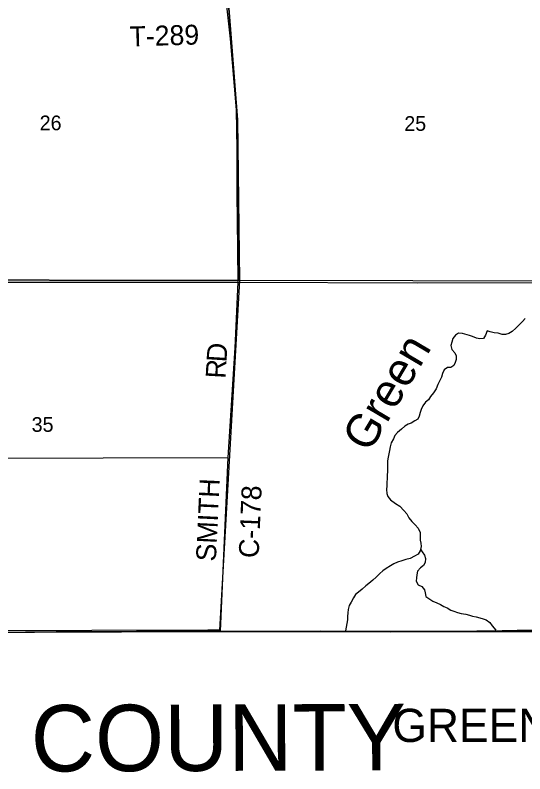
# Model space of a CAD drawing. Extents: x 1588073 to 2013523, y 1090242 to 1357120.
# Drawn here: x 1802549 to 1810221, y 1184806 to 1196224 of the extents above; entities that cross this region are included whole.
import ezdxf

# ---------------------------------------------------------------- set-up
doc = ezdxf.new("R2010")
doc.units = 0
for name, color, linetype in [('GM_X_Adjacent_County', 7, 'Continuous'), ('GM_X_Adjacent_County_Text', 7, 'Continuous'), ('GM_X_Corporation_Text', 7, 'Continuous'), ('GM_X_County', 7, 'Continuous'), ('GM_X_County_Road', 7, 'Continuous'), ('GM_X_County_Road_Text', 7, 'Continuous'), ('GM_X_Minor_River', 7, 'Continuous'), ('GM_X_Minor_River_Text', 7, 'Continuous'), ('GM_X_Section', 7, 'Continuous'), ('GM_X_Section_Text', 7, 'Continuous'), ('GM_X_Township', 7, 'Continuous'), ('GM_X_Township_Road', 7, 'Continuous'), ('GM_X_Township_Road_Text', 7, 'Continuous')]:
    doc.layers.add(name, color=color, linetype=linetype)

msp = doc.modelspace()

# ---------------------------------------------------------------- linework, layer by layer
at = {"layer": 'GM_X_Adjacent_County'}
msp.add_lwpolyline([(1774968, 1186130), (1777293, 1186285), (1779305, 1186460), (1784845, 1186614), (1788308, 1186703), (1790395, 1186767), (1792343, 1186826), (1794753, 1186884), (1796246, 1186911), (1798820, 1186925), (1800076, 1186928), (1800215, 1186926), (1805457, 1186950), (1805640, 1186950), (1808199, 1186945), (1810942, 1186950)], dxfattribs=at)
at = {"layer": 'GM_X_County'}
msp.add_lwpolyline([(1810942, 1186950), (1808199, 1186945), (1805640, 1186950), (1805457, 1186950), (1800215, 1186926), (1800076, 1186928), (1798820, 1186925), (1796246, 1186911), (1794753, 1186884), (1792343, 1186826), (1790395, 1186767), (1788308, 1186703), (1784845, 1186614), (1779305, 1186460), (1777293, 1186285), (1774968, 1186130)], dxfattribs=at)
at = {"layer": 'GM_X_County_Road'}
for points in [[(1805907, 1192205), (1805903, 1192713), (1805892, 1193545), (1805889, 1194205), (1805879, 1194801), (1805789, 1195868), (1805742, 1196318), (1805750, 1196512), (1805779, 1197232), (1805804, 1198282), (1805860, 1199754)], [(1800179, 1192225), (1801710, 1192206), (1803349, 1192206), (1804221, 1192206), (1805907, 1192205), (1808599, 1192198), (1811129, 1192202)], [(1805640, 1186955), (1805757, 1189568), (1805861, 1191219), (1805907, 1192205)], [(1802158, 1186937), (1802702, 1186941), (1803168, 1186947), (1803729, 1186950), (1804376, 1186955), (1804742, 1186957), (1805353, 1186958), (1805457, 1186957), (1805507, 1186957), (1805640, 1186955)], [(1805640, 1186955), (1805727, 1186954), (1806052, 1186954), (1806262, 1186954), (1806679, 1186955), (1807138, 1186956), (1807325, 1186954), (1807778, 1186955), (1807919, 1186955), (1808195, 1186953), (1808293, 1186953), (1808398, 1186952), (1808707, 1186953), (1808956, 1186955), (1809100, 1186954), (1809320, 1186954), (1809497, 1186956), (1809622, 1186957), (1809881, 1186962), (1810022, 1186964), (1810107, 1186967), (1810166, 1186968), (1810326, 1186966)]]:
    msp.add_lwpolyline(points, dxfattribs=at)
at = {"layer": 'GM_X_Minor_River'}
for points in [[(1810225, 1191658), (1810188, 1191613), (1810138, 1191561), (1810085, 1191512), (1810029, 1191462), (1809978, 1191431), (1809928, 1191417), (1809878, 1191420), (1809822, 1191438), (1809762, 1191445), (1809700, 1191458), (1809654, 1191474), (1809629, 1191410), (1809601, 1191356), (1809545, 1191355), (1809495, 1191362), (1809435, 1191386), (1809389, 1191401), (1809281, 1191434), (1809225, 1191439), (1809179, 1191409), (1809136, 1191357), (1809123, 1191305), (1809109, 1191253), (1809120, 1191193), (1809168, 1191143), (1809187, 1191096), (1809189, 1191044), (1809174, 1190998), (1809152, 1190952), (1809105, 1190923), (1809057, 1190921), (1809009, 1190888), (1808984, 1190832), (1808965, 1190778), (1808939, 1190714), (1808910, 1190666), (1808885, 1190602), (1808846, 1190539), (1808802, 1190487), (1808773, 1190435), (1808725, 1190398), (1808684, 1190346), (1808661, 1190290), (1808645, 1190242), (1808630, 1190188), (1808612, 1190142), (1808565, 1190121), (1808509, 1190083)], [(1808509, 1190083), (1808463, 1190068), (1808416, 1190036), (1808364, 1189993), (1808305, 1189943), (1808264, 1189896), (1808244, 1189848), (1808211, 1189788), (1808192, 1189728), (1808184, 1189670), (1808173, 1189624), (1808166, 1189572), (1808156, 1189516), (1808155, 1189400), (1808152, 1189354), (1808147, 1189300), (1808147, 1189253), (1808144, 1189191), (1808142, 1189139), (1808139, 1189083), (1808142, 1189027), (1808158, 1188981), (1808197, 1188932), (1808275, 1188873), (1808338, 1188832), (1808398, 1188770), (1808445, 1188719), (1808473, 1188657), (1808522, 1188604), (1808570, 1188555), (1808617, 1188501), (1808648, 1188438), (1808646, 1188374), (1808647, 1188324), (1808657, 1188278), (1808662, 1188228), (1808645, 1188162), (1808617, 1188112), (1808562, 1188084), (1808496, 1188047), (1808431, 1188032), (1808369, 1188014), (1808305, 1187991), (1808250, 1187968), (1808200, 1187934), (1808135, 1187895), (1808085, 1187863), (1808038, 1187821), (1807984, 1187768), (1807933, 1187722), (1807875, 1187673), (1807828, 1187635), (1807773, 1187584), (1807719, 1187538), (1807670, 1187505), (1807642, 1187457), (1807609, 1187389), (1807576, 1187339), (1807564, 1187277), (1807557, 1187227), (1807552, 1187175), (1807550, 1187125), (1807543, 1187069), (1807521, 1186960)], [(1808652, 1188188), (1808675, 1188145), (1808711, 1188097), (1808724, 1188045), (1808719, 1187989), (1808697, 1187941), (1808650, 1187907), (1808608, 1187855), (1808595, 1187801), (1808588, 1187755), (1808586, 1187705), (1808615, 1187651), (1808669, 1187626), (1808713, 1187576), (1808720, 1187528), (1808731, 1187475), (1808789, 1187433), (1808837, 1187406), (1808897, 1187381), (1808952, 1187353), (1809000, 1187324), (1809050, 1187302), (1809108, 1187269), (1809154, 1187254), (1809209, 1187236), (1809261, 1187221), (1809333, 1187208), (1809387, 1187196), (1809435, 1187181), (1809489, 1187167), (1809545, 1187152), (1809593, 1187137), (1809639, 1187123), (1809692, 1187086), (1809730, 1187034), (1809783, 1186968)]]:
    msp.add_lwpolyline(points, dxfattribs=at)
at = {"layer": 'GM_X_Section'}
for points in [[(1805790, 1197171), (1805767, 1196330), (1805897, 1194649), (1805928, 1192229), (1800197, 1192243), (1800287, 1194883), (1800482, 1196183), (1800489, 1197099)], [(1811404, 1197002), (1811151, 1192271), (1811147, 1192223), (1805928, 1192229), (1805897, 1194649), (1805767, 1196330), (1805790, 1197171)], [(1805928, 1192229), (1805627, 1186970), (1805447, 1186969), (1800200, 1186952), (1800065, 1186951), (1800197, 1192243)]]:
    msp.add_lwpolyline(points, close=True, dxfattribs=at)
at = {"layer": 'GM_X_Township'}
msp.add_lwpolyline([(1810942, 1186950), (1808199, 1186945), (1805640, 1186950), (1805457, 1186950), (1800215, 1186926), (1800076, 1186928), (1798820, 1186925), (1796246, 1186911), (1794753, 1186884), (1792343, 1186826), (1790395, 1186767), (1788308, 1186703), (1784845, 1186614), (1779305, 1186460), (1779302, 1188059), (1779276, 1189093), (1779294, 1192910), (1779323, 1195998), (1779346, 1197040), (1779404, 1199699), (1779489, 1202438), (1779542, 1205006), (1779632, 1207410), (1779873, 1213024)], dxfattribs=at)
at = {"layer": 'GM_X_Township_Road'}
msp.add_lwpolyline([(1794888, 1189566), (1800110, 1189554), (1805757, 1189568)], dxfattribs=at)

# ---------------------------------------------------------------- texts
at = {"layer": 'GM_X_Adjacent_County_Text'}
msp.add_text('SENECA COUNTY', height=1000, rotation=0.1984, dxfattribs=at).set_placement((1796916, 1184820))
at = {"layer": 'GM_X_Corporation_Text'}
msp.add_text('GREEN SPRINGS', height=500, rotation=0, dxfattribs=at).set_placement((1808227, 1185285))
at = {"layer": 'GM_X_County_Road_Text'}
for s, rotation, p in [('D', 86.4825, (1805729, 1190995)), ('R', 86.8175, (1805715, 1190749)), ('SMITH', 87.347, (1805570, 1187998)), ('C-178', 87.5227, (1806213, 1188049))]:
    msp.add_text(s, height=300, rotation=rotation, dxfattribs=at).set_placement(p)
at = {"layer": 'GM_X_Minor_River_Text'}
msp.add_text('Green', height=500.3, rotation=59.3515, dxfattribs=at).set_placement((1807878, 1189624))
at = {"layer": 'GM_X_Section_Text'}
for s, p in [('26', (1802918, 1194492)), ('25', (1808407, 1194483)), ('35', (1802797, 1189953))]:
    msp.add_text(s, height=221, rotation=0, dxfattribs=at).set_placement(p)
at = {"layer": 'GM_X_Township_Road_Text'}
msp.add_text('T-289', height=300, rotation=1.6433, dxfattribs=at).set_placement((1804275, 1195753))

doc.saveas('drawing.dxf')
